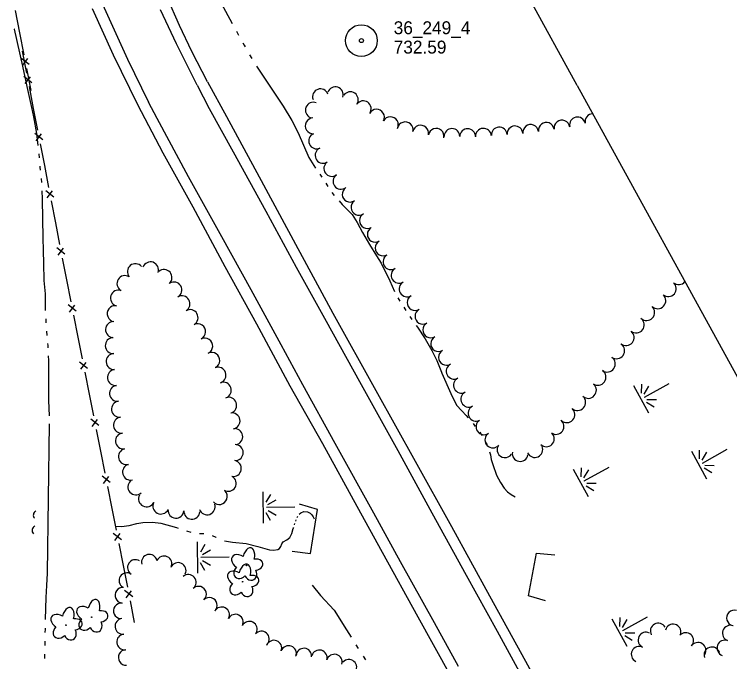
# Model space of a CAD drawing. Extents: x 589250 to 1188077, y 162953 to 363065.
# Drawn here: x 594436.7 to 594769.6, y 165742.7 to 166043.8 of the extents above; entities that cross this region are included whole.
import ezdxf

# ---------------------------------------------------------------- set-up
doc = ezdxf.new("R2010")
doc.units = 0
for name, color, linetype in [('E_DRN', 7, 'Continuous'), ('E_FEN_P', 7, 'Continuous'), ('E_LAND_TreeLine_P', 7, 'Continuous'), ('E_LAND_Vegetation', 7, 'Continuous'), ('E_MAP_Limits', 7, 'Continuous'), ('E_MAP_PassPoints', 7, 'Continuous'), ('E_RDWY', 7, 'Continuous'), ('E_RDWY_Gravel', 7, 'Continuous'), ('E_WAL', 7, 'Continuous'), ('E_WTR_FlowLine', 7, 'Continuous'), ('E_WTR_Wetland', 7, 'Continuous')]:
    doc.layers.add(name, color=color, linetype=linetype)

# ---------------------------------------------------------------- blocks, each defined once
blk = doc.blocks.new('POINT_DISPLAY')
blk.add_line((0, 0), (0, 0))

msp = doc.modelspace()

# ---------------------------------------------------------------- linework, layer by layer
at = {"layer": 'E_DRN'}
for centre, radius, start, end in [((594447.65, 165810.91), 2.09, 117.2972, 223.5574), ((594447.24, 165803.8), 2.24, 117.0908, 223.351)]:
    msp.add_arc(centre, radius, start, end, dxfattribs=at)
at = {"layer": 'E_FEN_P'}
for p, q in [((594439.25, 166035.26), (594437.21, 166045.54)), ((594441.28, 166024.97), (594439.25, 166035.26)), ((594442.53, 166016.46), (594440.57, 166026.61)), ((594443.66, 166020.48), (594439.84, 166023.44)), ((594440.51, 166020.02), (594443.03, 166023.32)), ((594444.57, 166008.32), (594442.54, 166018.61)), ((594444.87, 166012.02), (594441.1, 166014.95)), ((594441.76, 166011.58), (594444.26, 166014.82)), ((594445.71, 166000.03), (594443.75, 166010.18)), ((594447.68, 165989.88), (594445.71, 166000.03)), ((594450.01, 165985.43), (594446.25, 165988.37)), ((594446.9, 165985), (594449.4, 165988.24)), ((594450.86, 165973.45), (594448.89, 165983.6)), ((594452.82, 165963.3), (594450.86, 165973.45)), ((594455.16, 165958.85), (594451.39, 165961.79)), ((594452.05, 165958.42), (594454.55, 165961.66)), ((594456, 165946.87), (594454.04, 165957.02)), ((594457.96, 165936.72), (594456, 165946.87)), ((594460.3, 165932.27), (594456.54, 165935.21)), ((594457.19, 165931.84), (594459.69, 165935.08)), ((594461.19, 165920.29), (594459.18, 165930.43)), ((594463.2, 165910.15), (594461.19, 165920.29)), ((594465.55, 165905.72), (594461.78, 165908.64)), ((594462.44, 165905.27), (594464.93, 165908.52)), ((594466.45, 165893.73), (594464.44, 165903.87)), ((594468.45, 165883.59), (594466.45, 165893.73)), ((594470.81, 165879.16), (594467.03, 165882.08)), ((594467.7, 165878.71), (594470.19, 165881.96)), ((594471.7, 165867.17), (594469.7, 165877.32)), ((594473.71, 165857.03), (594471.7, 165867.17)), ((594476.06, 165852.6), (594472.29, 165855.52)), ((594472.96, 165852.15), (594475.44, 165855.4)), ((594476.96, 165840.61), (594474.95, 165850.76)), ((594478.97, 165830.47), (594476.96, 165840.61)), ((594481.32, 165826.04), (594477.55, 165828.96)), ((594478.21, 165825.59), (594480.7, 165828.84)), ((594482.22, 165814.06), (594480.21, 165824.2)), ((594484.22, 165803.91), (594482.22, 165814.06)), ((594486.58, 165799.48), (594482.8, 165802.4)), ((594483.47, 165799.03), (594485.96, 165802.28)), ((594487.47, 165787.5), (594485.46, 165797.64)), ((594489.48, 165777.35), (594487.47, 165787.5)), ((594491.83, 165772.92), (594488.06, 165775.84)), ((594488.72, 165772.47), (594491.21, 165775.73)), ((594492.73, 165760.94), (594490.72, 165771.08))]:
    msp.add_line(p, q, dxfattribs=at)
at = {"layer": 'E_LAND_TreeLine_P'}
for centre, radius, start, end in [((594579.17, 166005.48), 3.67, 20.2362, 200.2362), ((594586.1, 166006.42), 3.67, 341.8134, 161.8134), ((594593.07, 166004.11), 3.67, 325.0575, 145.0575), ((594575.84, 165999.26), 3.67, 67.9945, 247.9945), ((594599.09, 165999.9), 3.67, 325.0575, 145.0575), ((594605.29, 165995.98), 3.67, 331.4512, 151.4512), ((594705.95, 165993.89), 3.67, 91.7635, 191.9053), ((594575.81, 165991.97), 3.67, 92.1686, 272.1686), ((594611.75, 165992.47), 3.67, 331.4512, 151.4512), ((594691.56, 165990.89), 3.67, 7.9128, 187.9128), ((594698.76, 165992.37), 3.67, 11.9053, 191.9053), ((594618.61, 165990.08), 3.67, 348.2885, 168.2885), ((594625.81, 165988.59), 3.67, 348.2885, 168.2885), ((594633, 165987.1), 3.67, 348.2885, 168.2885), ((594640.35, 165987.01), 3.67, 359.5741, 179.5741), ((594647.69, 165986.95), 3.67, 359.5741, 179.5741), ((594655.03, 165987.13), 3.67, 4.2671, 184.2671), ((594662.36, 165987.67), 3.67, 4.2671, 184.2671), ((594669.69, 165988.22), 3.67, 4.2671, 184.2671), ((594677.01, 165988.87), 3.67, 7.9128, 187.9128), ((594684.28, 165989.88), 3.67, 7.9128, 187.9128), ((594577.41, 165984.94), 3.67, 113.9171, 293.9171), ((594580.39, 165978.22), 3.67, 113.9171, 293.9171), ((594584.44, 165972.12), 3.67, 125.8109, 305.8109), ((594588.74, 165966.16), 3.67, 125.8109, 305.8109), ((594592.98, 165960.16), 3.67, 124.0496, 304.0496), ((594597.09, 165954.07), 3.67, 124.0496, 304.0496), ((594601.03, 165947.87), 3.67, 119.8457, 299.8457), ((594604.68, 165941.5), 3.67, 119.8457, 299.8457), ((594608.34, 165935.13), 3.67, 119.8457, 299.8457), ((594612.01, 165928.76), 3.67, 120.5989, 300.5989), ((594493.05, 165924.11), 3.72, 39.3488, 219.3488), ((594500.11, 165924.96), 3.72, 340.7941, 160.7941), ((594506.38, 165921.4), 3.72, 310.7018, 130.7018), ((594615.75, 165922.44), 3.67, 120.5989, 300.5989), ((594488.21, 165918.59), 3.72, 58.5506, 238.5506), ((594510.99, 165915.59), 3.72, 300.3688, 120.3688), ((594619.49, 165916.11), 3.67, 120.5989, 300.5989), ((594741.07, 165916.21), 3.67, 229.1657, 49.1657), ((594745.87, 165921.77), 3.67, 229.1657, 321.6242), ((594485.22, 165911.84), 3.72, 71.9101, 251.9101), ((594514.75, 165909.17), 3.72, 300.3688, 120.3688), ((594623.21, 165909.77), 3.67, 119.793, 299.793), ((594736.1, 165910.67), 3.77, 226.6848, 46.6848), ((594483.66, 165904.59), 3.72, 81.4843, 261.4843), ((594730.92, 165905.18), 3.77, 226.6848, 46.6848), ((594518.51, 165902.75), 3.72, 300.3688, 120.3688), ((594626.86, 165903.4), 3.67, 119.793, 299.793), ((594482.9, 165897.2), 3.72, 88.1256, 268.1256), ((594726.09, 165899.39), 3.77, 231.3198, 51.3198), ((594522.04, 165896.21), 3.72, 296.2657, 116.2657), ((594630.51, 165897.02), 3.67, 119.793, 299.793), ((594721.37, 165893.5), 3.77, 231.3198, 51.3198), ((594482.77, 165889.77), 3.72, 93.1405, 273.1405), ((594525.33, 165889.53), 3.72, 296.2657, 116.2657), ((594634.16, 165890.64), 3.67, 119.793, 299.793), ((594637.81, 165884.27), 3.67, 119.793, 299.793), ((594716.95, 165887.39), 3.77, 234.7222, 54.7222), ((594483.18, 165882.34), 3.72, 93.1405, 273.1405), ((594528.63, 165882.86), 3.72, 296.2657, 116.2657), ((594712.59, 165881.23), 3.77, 234.7222, 54.7222), ((594641.37, 165877.84), 3.67, 117.5254, 297.5254), ((594483.84, 165874.93), 3.72, 97.1001, 277.1001), ((594531.49, 165876.01), 3.72, 289.5586, 109.5586), ((594708.23, 165875.07), 3.77, 234.7222, 54.7222), ((594644.76, 165871.32), 3.67, 117.5254, 297.5254), ((594484.76, 165867.55), 3.72, 97.1001, 277.1001), ((594533.98, 165869), 3.72, 289.5586, 109.5586), ((594703.8, 165868.97), 3.77, 228.358, 48.358), ((594648.16, 165864.81), 3.67, 117.5254, 297.5254), ((594536.48, 165861.98), 3.72, 289.5586, 109.5586), ((594698.79, 165863.33), 3.77, 228.358, 48.358), ((594485.68, 165860.17), 3.72, 97.1001, 277.1001), ((594651.56, 165858.29), 3.67, 117.5254, 297.5254), ((594538.04, 165854.73), 3.72, 279.716, 99.716), ((594693.77, 165857.69), 3.77, 228.358, 48.358), ((594486.6, 165852.78), 3.72, 97.1001, 277.1001), ((594655.25, 165851.95), 3.67, 124.2188, 304.2188), ((594688.81, 165852.14), 3.67, 233.9447, 53.9447), ((594539.3, 165847.4), 3.72, 279.716, 99.716), ((594487.52, 165845.4), 3.72, 97.1001, 277.1001), ((594659.38, 165845.87), 3.67, 124.2188, 304.2188), ((594684.3, 165846.36), 3.67, 224.8813, 44.8813), ((594488.91, 165838.1), 3.72, 104.9643, 284.9643), ((594539.52, 165839.96), 3.72, 271.3501, 91.3501), ((594665.07, 165841.32), 3.67, 144.4802, 324.4802), ((594678.94, 165841.39), 3.67, 204.1838, 24.1838), ((594672.1, 165839.54), 3.67, 169.8363, 349.8363), ((594490.83, 165830.92), 3.72, 104.9643, 284.9643), ((594538.64, 165832.61), 3.72, 259.2553, 79.2553), ((594536.23, 165825.68), 3.72, 239.6893, 59.6893), ((594493.31, 165824.02), 3.72, 131.4856, 311.4856), ((594532.11, 165819.55), 3.72, 221.9514, 41.9514), ((594498.28, 165818.5), 3.72, 153.0044, 333.0044), ((594504.91, 165815.12), 3.72, 153.0044, 333.0044), ((594526.45, 165814.79), 3.72, 198.8249, 18.8249), ((594511.95, 165813.23), 3.72, 175.8226, 355.8226), ((594519.37, 165812.69), 3.72, 175.8226, 355.8226), ((594499.57, 165788.98), 3.63, 13.2943, 193.2943), ((594506.4, 165788.22), 3.63, 335.2033, 155.2033), ((594493.03, 165786.55), 3.63, 57.4065, 237.4065), ((594513, 165785.18), 3.63, 335.2033, 155.2033), ((594489.12, 165780.43), 3.63, 57.4065, 237.4065), ((594517.69, 165779.63), 3.63, 310.1345, 130.1345), ((594522.46, 165774.15), 3.63, 314.0595, 134.0595), ((594487.2, 165773.61), 3.63, 84.6403, 264.6403), ((594527.51, 165768.92), 3.63, 314.0595, 134.0595), ((594486.52, 165766.38), 3.63, 84.6403, 264.6403), ((594533.2, 165764.54), 3.63, 332.1013, 152.1013), ((594539.63, 165761.14), 3.63, 333.1327, 153.1327), ((594771.83, 165763.05), 3.66, 75.2058, 255.2058), ((594487.22, 165759.15), 3.63, 96.4523, 276.4523), ((594546.11, 165757.86), 3.63, 333.1327, 153.1327), ((594736.34, 165757), 3.66, 28.7, 208.7), ((594743.26, 165756.56), 3.66, 345.6415, 165.6415), ((594769.91, 165755.99), 3.66, 69.8091, 249.8091), ((594488.04, 165751.93), 3.63, 96.4523, 276.4523), ((594551.73, 165753.29), 3.63, 319.3629, 139.3629), ((594730.65, 165752.78), 3.66, 64.169, 244.169), ((594749.17, 165752.55), 3.66, 317.3211, 137.3211), ((594557.54, 165749.05), 3.63, 339.7192, 159.7192), ((594754.87, 165748), 3.66, 328.1184, 148.1184), ((594767.38, 165749.11), 3.66, 69.8091, 249.8091), ((594488.78, 165744.7), 3.63, 92.3493, 272.3493), ((594564.36, 165746.53), 3.63, 339.7192, 159.7192), ((594571.47, 165745.34), 3.63, 355.6395, 175.6395), ((594578.67, 165744.53), 3.63, 344.2474, 164.2474), ((594727.46, 165746.19), 3.66, 64.169, 244.169), ((594761.31, 165745.9), 3.66, 18.2085, 198.2085), ((594585.67, 165742.55), 3.63, 344.2474, 164.2474), ((594592.42, 165740.13), 3.63, 319.3629, 139.3629)]:
    msp.add_arc(centre, radius, start, end, dxfattribs=at)
at = {"layer": 'E_LAND_Vegetation'}
for centre in [(594544.78, 165787.51), (594542.93, 165779.9), (594472.73, 165763.44), (594460.74, 165759.73)]:
    msp.add_circle(centre, 0.128, dxfattribs=at)
for centre, major_axis, ratio in [((594545.79, 165791.04), (-1.11, -4.62), 0.560249), ((594541.67, 165789.18), (3.58, -2.24), 0.691916), ((594543.95, 165783.44), (-1.11, -4.62), 0.560249), ((594548.77, 165787.86), (-3.59, -0.54), 0.716896), ((594539.82, 165781.57), (3.58, -2.24), 0.691916), ((594542.09, 165784.67), (2.59, 2.52), 0.782863), ((594546.61, 165783.97), (-1.59, 3.06), 0.832022), ((594546.93, 165780.26), (-3.59, -0.54), 0.716896), ((594540.24, 165777.07), (2.59, 2.52), 0.782863), ((594544.77, 165776.36), (-1.59, 3.06), 0.832022), ((594473.75, 165766.98), (-1.11, -4.62), 0.560249), ((594461.75, 165763.27), (-1.11, -4.62), 0.560249), ((594469.62, 165765.12), (3.58, -2.24), 0.691916), ((594457.63, 165761.4), (3.58, -2.24), 0.691916), ((594476.73, 165763.8), (-3.59, -0.54), 0.716896), ((594464.74, 165760.09), (-3.59, -0.54), 0.716896), ((594470.04, 165760.61), (2.59, 2.52), 0.782863), ((594474.57, 165759.91), (-1.59, 3.06), 0.832022), ((594458.05, 165756.9), (2.59, 2.52), 0.782863), ((594462.57, 165756.19), (-1.59, 3.06), 0.832022)]:
    msp.add_ellipse(centre, major_axis=major_axis, ratio=ratio, start_param=1.570796, end_param=4.712389, dxfattribs=at)
at = {"layer": 'E_MAP_Limits'}
for q in [(594652.77, 166094.62), (594826.1, 165778.78)]:
    msp.add_line((594698.56, 166010.79), q, dxfattribs=at)
at = {"layer": 'E_MAP_PassPoints'}
for radius in [7.38, 7.38, 7.38, 0.945, 0.945, 0.945]:
    msp.add_circle((594598.26, 166031.6), radius, dxfattribs=at)
at = {"layer": 'E_RDWY'}
for p, q in [((594477.75, 166048.54), (594489.45, 166022.92)), ((594512.21, 166030.03), (594504.74, 166045.95)), ((594521.87, 166010.8), (594512.21, 166030.03)), ((594489.45, 166022.92), (594499.12, 166003.03)), ((594521.87, 166010.8), (594527.44, 165999.96)), ((594503.19, 165995.29), (594499.12, 166003.03)), ((594527.44, 165999.96), (594538.51, 165979.79)), ((594517.8, 165968.21), (594503.19, 165995.29)), ((594538.51, 165979.79), (594553.71, 165952.2)), ((594533.26, 165940.26), (594517.8, 165968.21)), ((594553.71, 165952.2), (594567.86, 165926.26)), ((594546.89, 165915.61), (594533.26, 165940.26)), ((594567.86, 165926.26), (594581.09, 165902.44)), ((594560.89, 165890.07), (594546.89, 165915.61)), ((594581.09, 165902.44), (594598.19, 165871.64)), ((594571.05, 165871.55), (594560.89, 165890.07)), ((594586.01, 165844.28), (594571.05, 165871.55)), ((594598.19, 165871.64), (594615.13, 165840.95)), ((594604.04, 165811.74), (594586.01, 165844.28)), ((594615.13, 165840.95), (594631.03, 165812)), ((594616.5, 165789.11), (594604.04, 165811.74)), ((594631.03, 165812), (594647.01, 165782.93)), ((594632.2, 165760.84), (594616.5, 165789.11)), ((594647.01, 165782.93), (594661.39, 165756.88)), ((594643.36, 165740.55), (594632.2, 165760.84)), ((594661.39, 165756.88), (594676.02, 165730.38))]:
    msp.add_line(p, q, dxfattribs=at)
at = {"layer": 'E_RDWY_Gravel'}
for p, q in [((594513.55, 166038.67), (594507.58, 166052.28)), ((594482.95, 166024.81), (594473.11, 166046.38)), ((594519.35, 166026.53), (594513.55, 166038.67)), ((594494.26, 166001.75), (594482.95, 166024.81)), ((594526.6, 166012.41), (594519.35, 166026.53)), ((594526.6, 166012.41), (594535.44, 165996.25)), ((594505.99, 165979.31), (594494.26, 166001.75)), ((594535.44, 165996.25), (594552.73, 165964.47)), ((594519.95, 165954.06), (594505.99, 165979.31)), ((594552.73, 165964.47), (594567.58, 165936.94)), ((594534.89, 165926.35), (594519.95, 165954.06)), ((594567.58, 165936.94), (594584.99, 165904.82)), ((594549.52, 165899.65), (594534.89, 165926.35)), ((594584.99, 165904.82), (594604.98, 165868.83)), ((594565.09, 165870.89), (594549.52, 165899.65)), ((594580.25, 165844.03), (594565.09, 165870.89)), ((594604.98, 165868.83), (594623.19, 165836.03)), ((594596.23, 165814.93), (594580.25, 165844.03)), ((594623.19, 165836.03), (594640.16, 165805.6)), ((594607.99, 165793.47), (594596.23, 165814.93)), ((594640.16, 165805.6), (594657.86, 165773.4)), ((594624.67, 165763.44), (594607.99, 165793.47)), ((594657.86, 165773.4), (594674.63, 165743.02)), ((594639.74, 165736.37), (594624.67, 165763.44)), ((594674.63, 165743.02), (594692.78, 165710.11))]:
    msp.add_line(p, q, dxfattribs=at)
at = {"layer": 'E_WAL'}
for p, q in [((594577.79, 165813.47), (594569.48, 165815.94)), ((594574.52, 165793.05), (594577.79, 165813.47)), ((594566.03, 165794.15), (594574.52, 165793.05)), ((594675.93, 165773.42), (594679.7, 165793.16)), ((594679.7, 165793.16), (594688.17, 165792.47)), ((594683.93, 165771.09), (594675.93, 165773.42))]:
    msp.add_line(p, q, dxfattribs=at)
at = {"layer": 'E_WTR_FlowLine'}
for p, q in [((594532.96, 166049.05), (594538.09, 166039.57)), ((594436.76, 166036.91), (594436.73, 166037.03)), ((594440.77, 166019.66), (594436.76, 166036.91)), ((594540.1, 166035.93), (594541.11, 166034.12)), ((594543.14, 166030.49), (594543.69, 166029.51)), ((594543.69, 166029.51), (594544.15, 166028.68)), ((594546.17, 166025.04), (594547.18, 166023.23)), ((594442.73, 166010.2), (594440.77, 166019.66)), ((594549.36, 166019.69), (594554.33, 166012.22)), ((594554.33, 166012.22), (594561.86, 166001.11)), ((594444.85, 166000.5), (594442.73, 166010.2)), ((594445.82, 165996.16), (594444.85, 166000.5)), ((594561.86, 166001.11), (594565.84, 165994.49)), ((594447.16, 165988.34), (594445.82, 165996.16)), ((594565.84, 165994.49), (594568.87, 165988.76)), ((594447.8, 165982.83), (594447.16, 165988.34)), ((594568.87, 165988.76), (594573.79, 165977.18)), ((594448.25, 165978.9), (594448.24, 165979.01)), ((594448.41, 165977.09), (594448.25, 165978.9)), ((594573.79, 165977.18), (594576.92, 165972.33)), ((594448.8, 165972.79), (594448.75, 165973.26)), ((594448.96, 165971.35), (594448.8, 165972.79)), ((594449.61, 165965.62), (594449.39, 165967.53)), ((594578.83, 165969.49), (594579.81, 165968.09)), ((594581.71, 165965.24), (594582.61, 165963.78)), ((594449.84, 165957.95), (594449.75, 165961.77)), ((594584.47, 165960.91), (594585.59, 165959.62)), ((594449.95, 165948.54), (594449.84, 165957.95)), ((594587.83, 165957.02), (594589.29, 165955.33)), ((594589.29, 165955.33), (594593.94, 165950.72)), ((594593.94, 165950.72), (594596.27, 165947.07)), ((594450.2, 165940.09), (594449.95, 165948.54)), ((594596.27, 165947.07), (594598.77, 165942.39)), ((594598.77, 165942.39), (594601.95, 165936.84)), ((594450.3, 165933.89), (594450.2, 165940.09)), ((594601.95, 165936.84), (594601.96, 165936.83)), ((594601.96, 165936.83), (594605.26, 165931.48)), ((594450.4, 165928.08), (594450.3, 165933.89)), ((594605.26, 165931.48), (594607.42, 165928.04)), ((594450.7, 165920.04), (594450.4, 165928.08)), ((594607.42, 165928.04), (594611.43, 165919.87)), ((594451.17, 165913.76), (594450.7, 165920.04)), ((594611.43, 165919.87), (594613.67, 165914.97)), ((594451.29, 165906.03), (594451.17, 165913.76)), ((594615.23, 165911.93), (594616.13, 165910.47)), ((594617.94, 165907.56), (594618.86, 165906.12)), ((594451.63, 165900.27), (594451.52, 165902.19)), ((594620.77, 165903.28), (594621.77, 165901.89)), ((594623.78, 165899.11), (594624.31, 165898.36)), ((594624.31, 165898.36), (594627.95, 165892.94)), ((594452.08, 165894.51), (594451.93, 165896.43)), ((594452.46, 165889.83), (594452.39, 165890.68)), ((594627.95, 165892.94), (594630.97, 165887.53)), ((594452.51, 165888.76), (594452.46, 165889.83)), ((594630.97, 165887.53), (594633.39, 165882.8)), ((594452.82, 165882.85), (594452.71, 165884.92)), ((594452.74, 165876.32), (594452.82, 165882.85)), ((594633.39, 165882.8), (594635.56, 165877.34)), ((594635.56, 165877.34), (594635.7, 165877)), ((594452.74, 165864.2), (594452.74, 165876.32)), ((594635.7, 165877), (594639.78, 165867.42)), ((594639.78, 165867.42), (594642.52, 165862.07)), ((594453.08, 165857.04), (594452.74, 165864.2)), ((594642.52, 165862.07), (594644.91, 165859.36)), ((594644.91, 165859.36), (594646.91, 165857.19)), ((594646.91, 165857.19), (594647.92, 165856.11)), ((594452.98, 165853.32), (594452.04, 165783.85)), ((594650.17, 165853.53), (594651.21, 165852.17)), ((594653.3, 165849.45), (594653.74, 165848.88)), ((594653.74, 165848.88), (594654.22, 165848.01)), ((594655.88, 165845.01), (594656.71, 165843.52)), ((594657.9, 165840.32), (594658.34, 165838.97)), ((594658.34, 165838.97), (594658.69, 165836.82)), ((594658.69, 165836.82), (594659.32, 165834.47)), ((594659.32, 165834.47), (594661.08, 165829.44)), ((594661.08, 165829.44), (594662.9, 165826)), ((594662.9, 165826), (594664.69, 165823.5)), ((594664.69, 165823.5), (594666.27, 165821.71)), ((594666.27, 165821.71), (594667.96, 165820.5)), ((594667.96, 165820.5), (594669.72, 165819.47)), ((594569.32, 165811.37), (594569.99, 165812.03)), ((594569.99, 165812.03), (594571.45, 165812.52)), ((594571.45, 165812.52), (594573.12, 165812.48)), ((594573.12, 165812.48), (594574.41, 165811.81)), ((594574.41, 165811.81), (594575.18, 165810.99)), ((594575.18, 165810.99), (594575.78, 165810.03)), ((594493.75, 165806.97), (594496.46, 165807.41)), ((594496.46, 165807.41), (594500.96, 165807.57)), ((594500.96, 165807.57), (594504.98, 165807.09)), ((594567.65, 165808.13), (594567.85, 165808.71)), ((594568.34, 165809.83), (594568.64, 165810.36)), ((594575.78, 165810.03), (594576.32, 165809.17)), ((594483.64, 165805.7), (594486.65, 165805.65)), ((594486.65, 165805.65), (594490.22, 165806.13)), ((594490.22, 165806.13), (594493.75, 165806.97)), ((594504.98, 165807.09), (594512.19, 165805.12)), ((594512.19, 165805.12), (594512.96, 165804.87)), ((594565.91, 165802.4), (594566.55, 165804.64)), ((594566.55, 165804.64), (594566.72, 165805.22)), ((594567.07, 165806.39), (594567.24, 165806.98)), ((594516.87, 165803.58), (594518.82, 165802.94)), ((594522.85, 165802.36), (594524.64, 165802.33)), ((594524.64, 165802.33), (594524.91, 165802.31)), ((594528.85, 165801.43), (594530.48, 165800.65)), ((594564.89, 165800.45), (594565.91, 165802.4)), ((594530.48, 165800.65), (594530.7, 165800.54)), ((594534.46, 165798.92), (594538.3, 165798.32)), ((594538.3, 165798.32), (594544.63, 165797.66)), ((594544.63, 165797.66), (594550.01, 165796.29)), ((594560.69, 165796.25), (594561.26, 165797.59)), ((594561.26, 165797.59), (594561.76, 165798.41)), ((594561.76, 165798.41), (594563.5, 165799.37)), ((594563.5, 165799.37), (594564.89, 165800.45)), ((594550.01, 165796.29), (594555.44, 165794.71)), ((594555.44, 165794.71), (594557.26, 165794.61)), ((594557.26, 165794.61), (594559.31, 165794.86)), ((594559.31, 165794.86), (594560.16, 165795.31)), ((594560.16, 165795.31), (594560.69, 165796.25)), ((594452.04, 165783.85), (594451.77, 165778.12)), ((594451.77, 165778.12), (594451.38, 165772.6)), ((594575.26, 165778.36), (594579.25, 165773.58)), ((594451.38, 165772.6), (594451.14, 165762.39)), ((594579.25, 165773.58), (594585.58, 165766.75)), ((594585.58, 165766.75), (594591.23, 165757.61)), ((594451.03, 165757.93), (594451, 165756.35)), ((594451.04, 165758.36), (594451.03, 165757.93)), ((594591.23, 165757.61), (594593.42, 165754.18)), ((594450.92, 165752.32), (594450.89, 165750.31)), ((594595.67, 165750.65), (594596.79, 165748.88)), ((594450.78, 165746.28), (594450.71, 165744.26)), ((594599.01, 165745.33), (594600.09, 165743.54))]:
    msp.add_line(p, q, dxfattribs=at)
at = {"layer": 'E_WTR_Wetland'}
for p, q in [((594724.82, 165871.19), (594731.85, 165858.44)), ((594728.5, 165871.8), (594728.45, 165867.63)), ((594741.33, 165871.96), (594729.77, 165865.58)), ((594729.78, 165867.13), (594732.05, 165870.86)), ((594731.11, 165864.71), (594735.48, 165864.65)), ((594734.39, 165861.14), (594730.83, 165863.32)), ((594755.46, 165841.19), (594755.41, 165837.02)), ((594768.29, 165841.35), (594756.73, 165834.97)), ((594751.77, 165840.58), (594758.81, 165827.83)), ((594756.73, 165836.52), (594759, 165840.24)), ((594758.07, 165834.1), (594762.43, 165834.04)), ((594696.78, 165832.29), (594703.81, 165819.54)), ((594700.46, 165832.9), (594700.41, 165828.73)), ((594713.29, 165833.06), (594701.73, 165826.68)), ((594701.74, 165828.23), (594704.01, 165831.95)), ((594761.34, 165830.53), (594757.79, 165832.71)), ((594706.34, 165822.24), (594702.79, 165824.42)), ((594703.07, 165825.81), (594707.44, 165825.75)), ((594552.34, 165821.72), (594552.47, 165807.16)), ((594555.87, 165820.5), (594553.84, 165816.86)), ((594554.77, 165815.79), (594558.54, 165817.99)), ((594567.23, 165814.55), (594554.03, 165814.43)), ((594555.98, 165808.33), (594553.89, 165811.93)), ((594554.8, 165813.03), (594558.61, 165810.9)), ((594521.81, 165798.52), (594521.95, 165783.96)), ((594525.34, 165797.3), (594523.32, 165793.66)), ((594524.25, 165792.59), (594528.02, 165794.79)), ((594536.71, 165791.35), (594523.5, 165791.23)), ((594525.45, 165785.13), (594523.37, 165788.73)), ((594524.27, 165789.83), (594528.08, 165787.7)), ((594714.73, 165762.67), (594721.77, 165749.92)), ((594718.42, 165763.28), (594718.37, 165759.11)), ((594731.25, 165763.44), (594719.69, 165757.06)), ((594719.69, 165758.61), (594721.97, 165762.33)), ((594724.3, 165752.62), (594720.75, 165754.8)), ((594721.03, 165756.19), (594725.39, 165756.13))]:
    msp.add_line(p, q, dxfattribs=at)

# ---------------------------------------------------------------- block references
for p, rotation in [((594728.12, 165865.2), 61.10454685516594), ((594728.36, 165864.78), 61.10454685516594), ((594728.39, 165864.72), 61.10454685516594), ((594729.77, 165865.58), 61.10454685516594), ((594730.87, 165866.19), 61.10454685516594), ((594755.08, 165834.59), 61.10454685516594), ((594755.31, 165834.16), 61.10454685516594), ((594755.34, 165834.11), 61.10454685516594), ((594756.73, 165834.97), 61.10454685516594), ((594757.83, 165835.58), 61.10454685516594), ((594700.08, 165826.3), 61.10454685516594), ((594700.32, 165825.87), 61.10454685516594), ((594700.35, 165825.82), 61.10454685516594), ((594701.73, 165826.68), 61.10454685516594), ((594702.83, 165827.28), 61.10454685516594), ((594552.4, 165814.88), 89.47202838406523), ((594552.4, 165814.39), 89.47202838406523), ((594552.4, 165814.33), 89.47202838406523), ((594554.03, 165814.43), 89.47202838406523), ((594555.29, 165814.44), 89.47202838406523), ((594521.88, 165791.68), 89.47202838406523), ((594521.88, 165791.19), 89.47202838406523), ((594521.88, 165791.13), 89.47202838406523), ((594523.5, 165791.23), 89.47202838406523), ((594524.76, 165791.24), 89.47202838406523), ((594720.79, 165757.66), 61.10454685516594), ((594718.04, 165756.68), 61.10454685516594), ((594718.27, 165756.25), 61.10454685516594), ((594718.3, 165756.2), 61.10454685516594), ((594719.69, 165757.06), 61.10454685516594)]:
    msp.add_blockref('POINT_DISPLAY', p, dxfattribs=dict(at, rotation=rotation))

# ---------------------------------------------------------------- texts
at = {"layer": 'E_MAP_PassPoints'}
for s, p in [('36_249_4', (594613.26, 166034.58)), ('36_249_4', (594613.26, 166034.58)), ('36_249_4', (594613.26, 166034.58)), ('732.59', (594613.26, 166025.58)), ('732.59', (594613.26, 166025.58)), ('732.59', (594613.26, 166025.58))]:
    msp.add_text(s, height=6, dxfattribs=at).set_placement(p)

doc.saveas('drawing.dxf')
